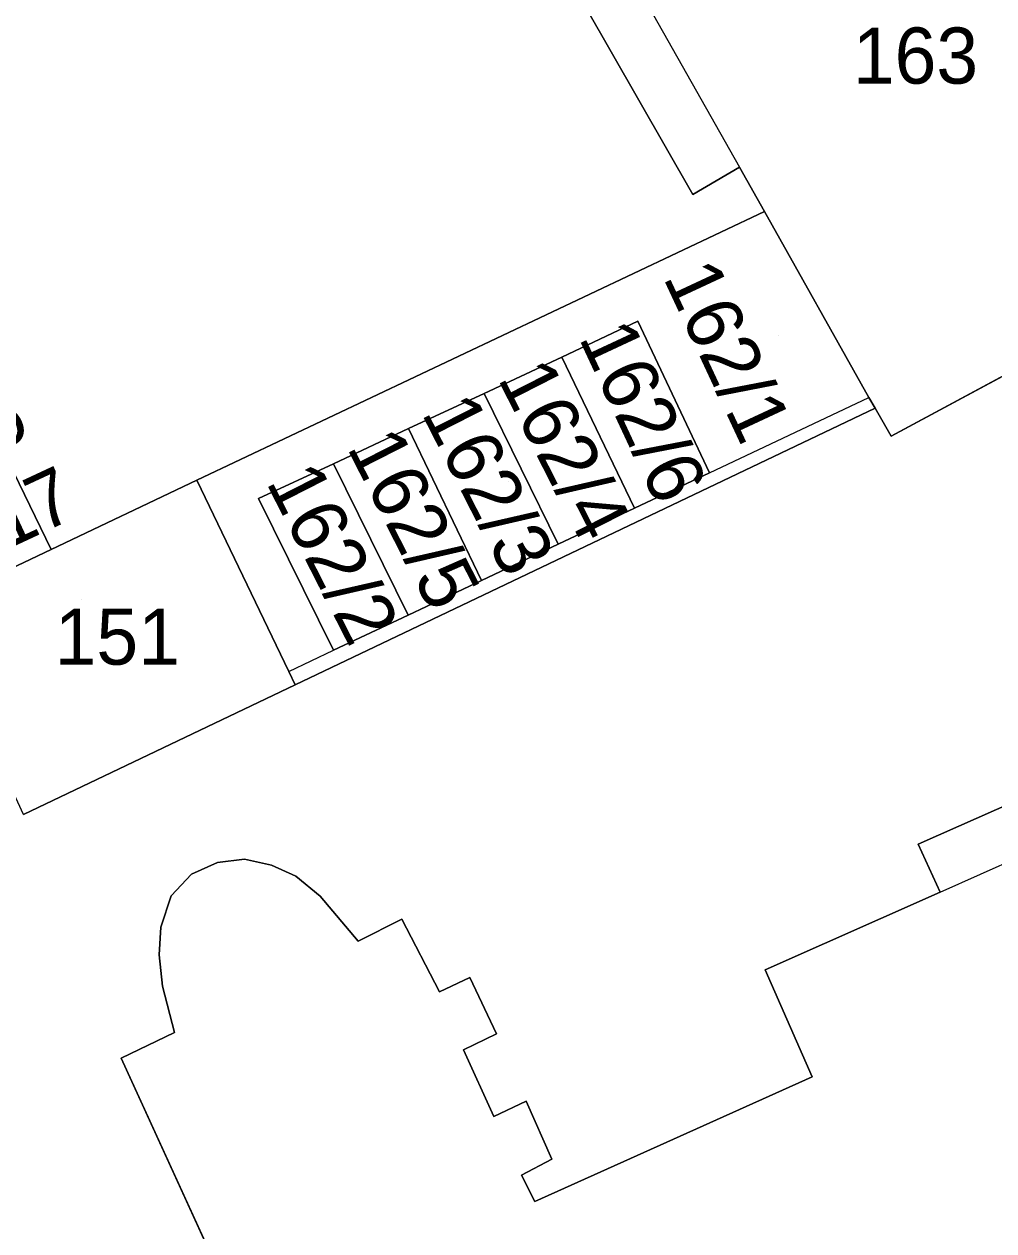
# Model space of a CAD drawing. Extents: x -264070 to -262271, y -1238894 to -1238141.
# Drawn here: x -263238.46 to -263203.93, y -1238614.43 to -1238571.44 of the extents above; entities that cross this region are included whole.
import ezdxf

# ---------------------------------------------------------------- set-up
doc = ezdxf.new("R2010")
doc.units = 0
for name, color, linetype in [('body_kn', 7, 'Continuous'), ('kladpar_druhypozemkov', 7, 'Continuous'), ('kladpar_hranice', 7, 'Continuous'), ('kladpar_parcelnecisla', 7, 'Continuous'), ('kladpar_plochy', 7, 'Continuous'), ('zappar_hrandruhpozemk', 7, 'Continuous')]:
    doc.layers.add(name, color=color, linetype=linetype)

msp = doc.modelspace()

# ---------------------------------------------------------------- linework, layer by layer
at = {"layer": 'body_kn'}
for p, q in [((-263212.99, -1238576.54), (-263212.99, -1238576.54)), ((-263214.65, -1238577.51), (-263214.65, -1238577.51)), ((-263212.1, -1238578.11), (-263212.1, -1238578.11)), ((-263212.1, -1238578.11), (-263212.1, -1238578.11)), ((-263216.61, -1238582.02), (-263216.61, -1238582.02)), ((-263216.61, -1238582.02), (-263216.61, -1238582.02)), ((-263219.32, -1238583.3), (-263219.32, -1238583.3)), ((-263219.32, -1238583.3), (-263219.32, -1238583.3)), ((-263222.08, -1238584.6), (-263222.08, -1238584.6)), ((-263222.08, -1238584.6), (-263222.08, -1238584.6)), ((-263208.38, -1238584.74), (-263208.38, -1238584.74)), ((-263208.16, -1238585.12), (-263208.16, -1238585.12)), ((-263208.16, -1238585.12), (-263208.16, -1238585.12)), ((-263224.78, -1238585.85), (-263224.78, -1238585.85)), ((-263224.78, -1238585.85), (-263224.78, -1238585.85)), ((-263207.59, -1238586.12), (-263207.59, -1238586.12)), ((-263227.45, -1238587.1), (-263227.45, -1238587.1)), ((-263232.31, -1238587.69), (-263232.31, -1238587.69)), ((-263214.06, -1238587.42), (-263214.06, -1238587.42)), ((-263214.06, -1238587.42), (-263214.06, -1238587.42)), ((-263230.12, -1238588.34), (-263230.12, -1238588.34)), ((-263216.73, -1238588.68), (-263216.73, -1238588.68)), ((-263237.5, -1238590.16), (-263237.5, -1238590.16)), ((-263237.5, -1238590.16), (-263237.5, -1238590.16)), ((-263219.44, -1238589.97), (-263219.44, -1238589.97)), ((-263222.17, -1238591.26), (-263222.17, -1238591.26)), ((-263224.79, -1238592.49), (-263224.79, -1238592.49)), ((-263224.79, -1238592.49), (-263224.79, -1238592.49)), ((-263227.44, -1238593.74), (-263227.44, -1238593.74)), ((-263229.04, -1238594.5), (-263229.04, -1238594.5)), ((-263229.04, -1238594.5), (-263229.04, -1238594.5)), ((-263228.81, -1238594.98), (-263228.81, -1238594.98)), ((-263206.62, -1238600.65), (-263206.62, -1238600.65)), ((-263231.57, -1238601.31), (-263231.57, -1238601.31)), ((-263230.61, -1238601.19), (-263230.61, -1238601.19)), ((-263229.65, -1238601.4), (-263229.65, -1238601.4)), ((-263232.5, -1238601.72), (-263232.5, -1238601.72)), ((-263228.79, -1238601.79), (-263228.79, -1238601.79)), ((-263233.22, -1238602.5), (-263233.22, -1238602.5)), ((-263227.92, -1238602.51), (-263227.92, -1238602.51)), ((-263205.84, -1238602.36), (-263205.84, -1238602.36)), ((-263205.84, -1238602.36), (-263205.84, -1238602.36)), ((-263233.59, -1238603.61), (-263233.59, -1238603.61)), ((-263225.01, -1238603.33), (-263225.01, -1238603.33)), ((-263226.57, -1238604.11), (-263226.57, -1238604.11)), ((-263233.65, -1238604.6), (-263233.65, -1238604.6)), ((-263212.07, -1238605.13), (-263212.07, -1238605.13)), ((-263233.53, -1238605.71), (-263233.53, -1238605.71)), ((-263222.59, -1238605.4), (-263222.59, -1238605.4)), ((-263223.67, -1238605.91), (-263223.67, -1238605.91)), ((-263233.11, -1238607.36), (-263233.11, -1238607.36)), ((-263221.64, -1238607.41), (-263221.64, -1238607.41)), ((-263235, -1238608.28), (-263235, -1238608.28)), ((-263222.81, -1238607.98), (-263222.81, -1238607.98)), ((-263210.4, -1238608.94), (-263210.4, -1238608.94)), ((-263220.59, -1238609.81), (-263220.59, -1238609.81)), ((-263221.73, -1238610.35), (-263221.73, -1238610.35)), ((-263221.73, -1238610.35), (-263221.73, -1238610.35)), ((-263219.67, -1238611.88), (-263219.67, -1238611.88)), ((-263220.75, -1238612.45), (-263220.75, -1238612.45)), ((-263220.27, -1238613.38), (-263220.27, -1238613.38))]:
    msp.add_line(p, q, dxfattribs=at)
at = {"layer": 'kladpar_druhypozemkov'}
for p, q in [((-263211.61, -1238582.52), (-263211.61, -1238582.52)), ((-263215.94, -1238585.02), (-263215.94, -1238585.02)), ((-263218.59, -1238586.35), (-263218.59, -1238586.35)), ((-263221.21, -1238587.75), (-263221.21, -1238587.75)), ((-263223.93, -1238588.8), (-263223.93, -1238588.8)), ((-263226.65, -1238590.12), (-263226.65, -1238590.12)), ((-263236.41, -1238591.95), (-263236.41, -1238591.95))]:
    msp.add_line(p, q, dxfattribs=at)
at = {"layer": 'kladpar_hranice'}
for p, q in [((-263232.31, -1238587.69), (-263212.1, -1238578.11)), ((-263228.81, -1238594.98), (-263208.16, -1238585.12))]:
    msp.add_line(p, q, dxfattribs=at)
for points in [[(-263240.8, -1238530.62), (-263230.77, -1238549.31), (-263230.45, -1238549.13), (-263228.91, -1238548.28), (-263224.74, -1238555.68), (-263226.46, -1238556.64), (-263222.58, -1238563.52), (-263220.87, -1238562.56), (-263218.31, -1238567.11), (-263216.79, -1238569.8), (-263218.5, -1238570.79), (-263214.65, -1238577.51), (-263212.99, -1238576.54), (-263212.1, -1238578.11), (-263232.31, -1238587.69), (-263237.5, -1238590.16), (-263238.83, -1238587.41)], [(-263204.79, -1238559.85), (-263194.22, -1238578.86), (-263194.19, -1238578.91), (-263194.51, -1238579.08), (-263207.59, -1238586.12), (-263208.16, -1238585.12), (-263208.38, -1238584.74), (-263212.1, -1238578.11), (-263212.99, -1238576.54), (-263214.65, -1238577.51), (-263218.5, -1238570.79), (-263216.79, -1238569.8), (-263218.31, -1238567.11), (-263204.79, -1238559.85)], [(-263212.1, -1238578.11), (-263208.38, -1238584.74), (-263208.16, -1238585.12), (-263228.81, -1238594.98), (-263229.04, -1238594.5), (-263232.31, -1238587.69)], [(-263208.16, -1238585.12), (-263207.59, -1238586.12), (-263194.51, -1238579.08), (-263194.19, -1238578.91), (-263189.95, -1238586.45), (-263190.29, -1238586.69), (-263190.46, -1238586.81), (-263188.97, -1238590.2), (-263188.55, -1238589.99), (-263175.51, -1238614.21), (-263175.99, -1238614.39), (-263173.93, -1238618.11)], [(-263214.06, -1238587.42), (-263216.61, -1238582.02), (-263219.32, -1238583.3), (-263222.08, -1238584.6), (-263224.78, -1238585.85), (-263227.45, -1238587.1), (-263230.12, -1238588.34), (-263227.44, -1238593.74), (-263224.79, -1238592.49), (-263222.17, -1238591.26), (-263219.44, -1238589.97), (-263216.73, -1238588.68), (-263214.06, -1238587.42)], [(-263216.61, -1238582.02), (-263214.06, -1238587.42), (-263216.73, -1238588.68), (-263219.32, -1238583.3), (-263216.61, -1238582.02)], [(-263219.32, -1238583.3), (-263216.73, -1238588.68), (-263219.44, -1238589.97), (-263222.08, -1238584.6), (-263219.32, -1238583.3)], [(-263222.08, -1238584.6), (-263219.44, -1238589.97), (-263222.17, -1238591.26), (-263224.78, -1238585.85), (-263222.08, -1238584.6)], [(-263224.78, -1238585.85), (-263222.17, -1238591.26), (-263224.79, -1238592.49), (-263227.45, -1238587.1), (-263224.78, -1238585.85)], [(-263224.79, -1238592.49), (-263227.44, -1238593.74), (-263230.12, -1238588.34), (-263227.45, -1238587.1), (-263224.79, -1238592.49)], [(-263238.83, -1238587.41), (-263237.5, -1238590.16), (-263241.88, -1238592.23), (-263243.36, -1238592.94), (-263244.67, -1238590.16), (-263238.83, -1238587.41)], [(-263237.5, -1238590.16), (-263232.31, -1238587.69), (-263229.04, -1238594.5), (-263228.81, -1238594.98), (-263238.48, -1238599.6), (-263241.88, -1238592.23), (-263237.5, -1238590.16)], [(-263238.48, -1238599.6), (-263228.81, -1238594.98)], [(-263221.73, -1238610.35), (-263220.59, -1238609.81), (-263219.67, -1238611.88), (-263220.75, -1238612.45), (-263220.27, -1238613.38), (-263210.4, -1238608.94), (-263212.07, -1238605.13), (-263205.84, -1238602.36), (-263206.62, -1238600.65), (-263203.11, -1238599.1), (-263202.25, -1238600.76), (-263194.67, -1238597.4), (-263184.17, -1238620.32)], [(-263203.11, -1238599.1), (-263206.62, -1238600.65), (-263205.84, -1238602.36), (-263212.07, -1238605.13), (-263210.4, -1238608.94), (-263220.27, -1238613.38), (-263220.75, -1238612.45), (-263219.67, -1238611.88), (-263220.59, -1238609.81), (-263221.73, -1238610.35), (-263222.81, -1238607.98), (-263221.64, -1238607.41), (-263222.59, -1238605.4), (-263223.67, -1238605.91), (-263225.01, -1238603.33), (-263226.57, -1238604.11), (-263227.92, -1238602.51), (-263228.79, -1238601.79), (-263229.65, -1238601.4), (-263230.61, -1238601.19), (-263231.57, -1238601.31), (-263232.5, -1238601.72), (-263233.22, -1238602.5), (-263233.59, -1238603.61), (-263233.65, -1238604.6), (-263233.53, -1238605.71), (-263233.11, -1238607.36), (-263235, -1238608.28), (-263230.29, -1238618.6)], [(-263230.29, -1238618.6), (-263235, -1238608.28), (-263233.11, -1238607.36), (-263233.53, -1238605.71), (-263233.65, -1238604.6), (-263233.59, -1238603.61), (-263233.22, -1238602.5), (-263232.5, -1238601.72), (-263231.57, -1238601.31), (-263230.61, -1238601.19), (-263229.65, -1238601.4), (-263228.79, -1238601.79), (-263227.92, -1238602.51), (-263226.57, -1238604.11), (-263225.01, -1238603.33), (-263223.67, -1238605.91), (-263222.59, -1238605.4), (-263221.64, -1238607.41), (-263222.81, -1238607.98), (-263221.73, -1238610.35)]]:
    msp.add_lwpolyline(points, dxfattribs=at)
at = {"layer": 'kladpar_plochy'}
for p, q in [((-263218.5, -1238570.79), (-263214.65, -1238577.51)), ((-263214.65, -1238577.51), (-263212.99, -1238576.54)), ((-263212.99, -1238576.54), (-263212.1, -1238578.11)), ((-263232.31, -1238587.69), (-263212.1, -1238578.11)), ((-263212.1, -1238578.11), (-263232.31, -1238587.69)), ((-263212.1, -1238578.11), (-263208.38, -1238584.74)), ((-263207.59, -1238586.12), (-263194.51, -1238579.08)), ((-263216.61, -1238582.02), (-263219.32, -1238583.3)), ((-263214.06, -1238587.42), (-263216.61, -1238582.02)), ((-263219.32, -1238583.3), (-263222.08, -1238584.6)), ((-263222.08, -1238584.6), (-263224.78, -1238585.85)), ((-263208.16, -1238585.12), (-263228.81, -1238594.98)), ((-263228.81, -1238594.98), (-263208.16, -1238585.12)), ((-263208.38, -1238584.74), (-263208.16, -1238585.12)), ((-263208.16, -1238585.12), (-263207.59, -1238586.12)), ((-263224.78, -1238585.85), (-263227.45, -1238587.1)), ((-263227.45, -1238587.1), (-263230.12, -1238588.34)), ((-263237.5, -1238590.16), (-263238.83, -1238587.41)), ((-263232.31, -1238587.69), (-263237.5, -1238590.16)), ((-263229.04, -1238594.5), (-263232.31, -1238587.69)), ((-263216.73, -1238588.68), (-263214.06, -1238587.42)), ((-263230.12, -1238588.34), (-263227.44, -1238593.74)), ((-263219.44, -1238589.97), (-263216.73, -1238588.68)), ((-263222.17, -1238591.26), (-263219.44, -1238589.97)), ((-263224.79, -1238592.49), (-263222.17, -1238591.26)), ((-263227.44, -1238593.74), (-263224.79, -1238592.49)), ((-263228.81, -1238594.98), (-263229.04, -1238594.5)), ((-263238.48, -1238599.6), (-263228.81, -1238594.98)), ((-263203.11, -1238599.1), (-263206.62, -1238600.65)), ((-263206.62, -1238600.65), (-263205.84, -1238602.36)), ((-263231.57, -1238601.31), (-263232.5, -1238601.72)), ((-263230.61, -1238601.19), (-263231.57, -1238601.31)), ((-263229.65, -1238601.4), (-263230.61, -1238601.19)), ((-263228.79, -1238601.79), (-263229.65, -1238601.4)), ((-263232.5, -1238601.72), (-263233.22, -1238602.5)), ((-263227.92, -1238602.51), (-263228.79, -1238601.79)), ((-263233.22, -1238602.5), (-263233.59, -1238603.61)), ((-263226.57, -1238604.11), (-263227.92, -1238602.51)), ((-263205.84, -1238602.36), (-263212.07, -1238605.13)), ((-263233.59, -1238603.61), (-263233.65, -1238604.6)), ((-263225.01, -1238603.33), (-263226.57, -1238604.11)), ((-263223.67, -1238605.91), (-263225.01, -1238603.33)), ((-263233.65, -1238604.6), (-263233.53, -1238605.71)), ((-263212.07, -1238605.13), (-263210.4, -1238608.94)), ((-263233.53, -1238605.71), (-263233.11, -1238607.36)), ((-263222.59, -1238605.4), (-263223.67, -1238605.91)), ((-263221.64, -1238607.41), (-263222.59, -1238605.4)), ((-263233.11, -1238607.36), (-263235, -1238608.28)), ((-263222.81, -1238607.98), (-263221.64, -1238607.41)), ((-263235, -1238608.28), (-263230.29, -1238618.6)), ((-263221.73, -1238610.35), (-263222.81, -1238607.98)), ((-263210.4, -1238608.94), (-263220.27, -1238613.38)), ((-263220.59, -1238609.81), (-263221.73, -1238610.35)), ((-263219.67, -1238611.88), (-263220.59, -1238609.81)), ((-263220.75, -1238612.45), (-263219.67, -1238611.88)), ((-263220.27, -1238613.38), (-263220.75, -1238612.45))]:
    msp.add_line(p, q, dxfattribs=at)
for points in [[(-263204.79, -1238559.85), (-263194.22, -1238578.86), (-263194.19, -1238578.91), (-263194.51, -1238579.08), (-263207.59, -1238586.12), (-263208.16, -1238585.12), (-263208.38, -1238584.74), (-263212.1, -1238578.11), (-263212.99, -1238576.54), (-263214.65, -1238577.51), (-263218.5, -1238570.79), (-263216.79, -1238569.8), (-263218.31, -1238567.11)], [(-263216.61, -1238582.02), (-263214.06, -1238587.42), (-263216.73, -1238588.68), (-263219.32, -1238583.3)], [(-263219.32, -1238583.3), (-263216.73, -1238588.68), (-263219.44, -1238589.97), (-263222.08, -1238584.6)], [(-263222.08, -1238584.6), (-263219.44, -1238589.97), (-263222.17, -1238591.26), (-263224.78, -1238585.85)], [(-263224.78, -1238585.85), (-263222.17, -1238591.26), (-263224.79, -1238592.49), (-263227.45, -1238587.1)], [(-263224.79, -1238592.49), (-263227.44, -1238593.74), (-263230.12, -1238588.34), (-263227.45, -1238587.1)], [(-263238.83, -1238587.41), (-263237.5, -1238590.16), (-263241.88, -1238592.23), (-263243.36, -1238592.94), (-263244.67, -1238590.16)], [(-263237.5, -1238590.16), (-263232.31, -1238587.69), (-263229.04, -1238594.5), (-263228.81, -1238594.98), (-263238.48, -1238599.6), (-263241.88, -1238592.23)]]:
    msp.add_lwpolyline(points, close=True, dxfattribs=at)
msp.add_lwpolyline([(-263230.29, -1238618.6), (-263235, -1238608.28), (-263233.11, -1238607.36), (-263233.53, -1238605.71), (-263233.65, -1238604.6), (-263233.59, -1238603.61), (-263233.22, -1238602.5), (-263232.5, -1238601.72), (-263231.57, -1238601.31), (-263230.61, -1238601.19), (-263229.65, -1238601.4), (-263228.79, -1238601.79), (-263227.92, -1238602.51), (-263226.57, -1238604.11), (-263225.01, -1238603.33), (-263223.67, -1238605.91), (-263222.59, -1238605.4), (-263221.64, -1238607.41), (-263222.81, -1238607.98), (-263221.73, -1238610.35), (-263220.59, -1238609.81), (-263219.67, -1238611.88), (-263220.75, -1238612.45), (-263220.27, -1238613.38), (-263210.4, -1238608.94), (-263212.07, -1238605.13), (-263205.84, -1238602.36), (-263206.62, -1238600.65), (-263203.11, -1238599.1)], dxfattribs=at)
at = {"layer": 'zappar_hrandruhpozemk'}
for p, q in [((-263216.79, -1238569.8), (-263212.99, -1238576.54)), ((-263214.06, -1238587.42), (-263208.38, -1238584.74)), ((-263229.04, -1238594.5), (-263227.44, -1238593.74)), ((-263205.84, -1238602.36), (-263202.25, -1238600.76))]:
    msp.add_line(p, q, dxfattribs=at)

# ---------------------------------------------------------------- texts
at = {"layer": 'kladpar_parcelnecisla'}
for s, p in [('163', (-263208.952, -1238573.56)), ('151', (-263237.375, -1238594.26))]:
    msp.add_text(s, height=2, dxfattribs=at).set_placement(p)
for s, rotation, p in [('162/1', 295, (-263215.724, -1238580.456)), ('162/6', 295, (-263218.727, -1238582.605)), ('162/4', 297, (-263221.618, -1238584.053)), ('161/16', 25, (-263245.59, -1238589.557)), ('162/3', 297, (-263224.325, -1238585.292)), ('162/5', 297, (-263226.983, -1238586.514)), ('161/17', 25, (-263243.867, -1238592.397)), ('162/2', 297, (-263229.867, -1238587.746))]:
    msp.add_text(s, height=2, rotation=rotation, dxfattribs=at).set_placement(p)

doc.saveas('drawing.dxf')
